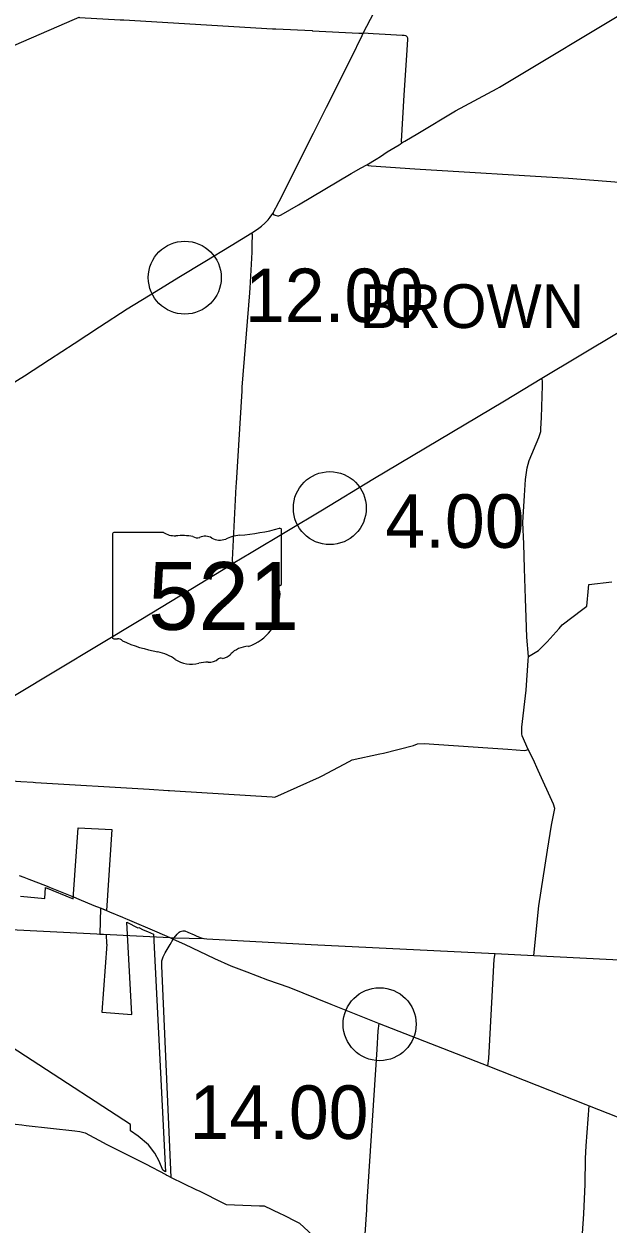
# Model space of a CAD drawing. Extents: x 1597222 to 1925846, y 496284 to 911751.
# Drawn here: x 1821840 to 1833850, y 827893 to 852560 of the extents above; entities that cross this region are included whole.
import ezdxf

# ---------------------------------------------------------------- set-up
doc = ezdxf.new("R2010")
doc.units = 0
for name, color, linetype in [('Default', 7, 'Continuous'), ('GM_X_Corporation', 7, 'Continuous'), ('GM_X_County_Road', 7, 'Continuous'), ('GM_X_State_Route', 7, 'Continuous'), ('GM_X_State_Shield', 7, 'Continuous'), ('GM_X_Township', 7, 'Continuous'), ('GM_X_Township_Road', 7, 'Continuous'), ('GM_X_Township_Text', 7, 'Continuous'), ('GM_X_US_Route', 7, 'Continuous')]:
    doc.layers.add(name, color=color, linetype=linetype)

msp = doc.modelspace()

# ---------------------------------------------------------------- linework, layer by layer
at = {"layer": 'Default'}
for centre in [(1825146, 847346), (1828129, 842608), (1829153, 832000)]:
    msp.add_circle(centre, 750, dxfattribs=at)
at = {"layer": 'GM_X_Corporation'}
msp.add_lwpolyline([(1821769, 834633), (1822268, 834587), (1822281, 834808), (1822854, 834577), (1822956, 836039), (1823645, 836005), (1823540, 834336), (1823415, 834383), (1823397, 833851), (1823528, 833845), (1823535, 833649), (1823542, 833643), (1823444, 832245), (1824058, 832202), (1823955, 834094), (1824182, 833983), (1824200, 833986), (1824290, 833942), (1824382, 833903), (1824500, 833849), (1824747, 828967), (1824696, 828999), (1824623, 829186), (1824531, 829351), (1824401, 829520), (1824191, 829701), (1824029, 829809), (1824031, 829939), (1819982, 832569)], dxfattribs=at)
at = {"layer": 'GM_X_County_Road'}
for points in [[(1827483, 848845), (1828569, 849486), (1828773, 849606), (1828890, 849668)], [(1828890, 849668), (1828890, 849668), (1828924, 849648), (1828977, 849643), (1829879, 849585), (1833037, 849389), (1834076, 849311), (1834469, 849288), (1834642, 849380), (1834781, 849392), (1836063, 849299), (1838431, 849174), (1838783, 849153), (1838998, 849141)], [(1826954, 848664), (1826976, 848639), (1827002, 848628), (1827054, 848615), (1827084, 848617), (1827126, 848635), (1827483, 848845)], [(1824834, 836804), (1824939, 836797), (1826941, 836673), (1827000, 836670), (1827915, 837079), (1827969, 837103), (1828528, 837401), (1828591, 837434), (1829159, 837555), (1829234, 837570), (1829847, 837731), (1829932, 837765), (1830068, 837770), (1831380, 837679), (1831789, 837651), (1832132, 837627), (1832164, 837633), (1832207, 837647), (1832086, 837925), (1832077, 837968), (1832081, 838107), (1832167, 838864), (1832211, 839479), (1832217, 839559), (1832354, 839640), (1832420, 839679), (1832530, 839793), (1832596, 839862), (1832843, 840137), (1832910, 840211), (1833329, 840531), (1833411, 840594), (1833446, 840962), (1833453, 841041), (1833926, 841092)], [(1820825, 837049), (1820913, 837042), (1821680, 836994), (1821777, 836987), (1822028, 836972), (1822074, 836969)], [(1822074, 836969), (1824417, 836829)], [(1824417, 836829), (1824803, 836806), (1824834, 836804), (1824834, 836804)], [(1833284, 827097), (1833354, 828099), (1833377, 828710), (1833389, 829242), (1833401, 829499), (1833463, 830322)]]:
    msp.add_lwpolyline(points, dxfattribs=at)
at = {"layer": 'GM_X_State_Route'}
for points in [[(1824240, 840319), (1825270, 840939), (1826096, 841440), (1826142, 841474), (1826514, 841694), (1827976, 842576), (1829017, 843200), (1831719, 844816), (1832490, 845282), (1838868, 849097), (1838914, 849121), (1838998, 849141), (1839418, 849116)], [(1820468, 838053), (1820655, 838166), (1821648, 838759), (1824240, 840319)]]:
    msp.add_lwpolyline(points, dxfattribs=at)
at = {"layer": 'GM_X_State_Shield'}
for p, q in [((1827137, 841053), (1827137, 842159)), ((1827137, 841053), (1827137, 842159)), ((1823657, 842070), (1823657, 839957)), ((1823657, 842070), (1823657, 839957)), ((1824710, 842107), (1823691, 842107)), ((1824710, 842107), (1823691, 842107)), ((1827137, 841054), (1827137, 841053)), ((1827137, 841054), (1827137, 841053))]:
    msp.add_line(p, q, dxfattribs=at)
for centre, major_axis, start_param, end_param in [((1825898, 844988), (3691, 0), 4.814394, 5.042369), ((1825898, 844988), (3691, 0), 4.814394, 5.042369), ((1827099, 842163), (38.7, 0), 6.141152, 7.989035), ((1827099, 842163), (38.7, 0), 6.141152, 7.989035), ((1823697, 842075), (40.3, 0), 1.712693, 3.28349), ((1823697, 842075), (40.3, 0), 1.712693, 3.28349), ((1824953, 842352), (391, 0), 4.042523, 4.731795), ((1824953, 842352), (391, 0), 4.042523, 4.731795), ((1825083, 840920), (1404, 0), 1.404758, 1.657858), ((1825083, 840920), (1404, 0), 1.404758, 1.657858), ((1825402, 842086), (113, 0), 3.836095, 5.185415), ((1825402, 842086), (113, 0), 3.836095, 5.185415), ((1825567, 841841), (235, 0), 0.950623, 2.079405), ((1825567, 841841), (235, 0), 0.950623, 2.079405), ((1825870, 842176), (282, 0), 4.081561, 5.145723), ((1825870, 842176), (282, 0), 4.081561, 5.145723), ((1826368, 841461), (743, 0), 1.699011, 2.107814), ((1826368, 841461), (743, 0), 1.699011, 2.107814), ((1827128, 840972), (60, 0), 1.883978, 3.671073), ((1827128, 840972), (60, 0), 1.883978, 3.671073), ((1826747, 840833), (360, 0), 5.934695, 6.695948), ((1826747, 840833), (360, 0), 5.934695, 6.695948), ((1827096, 841049), (41.5, 0), 5.05454, 6.418171), ((1827096, 841049), (41.5, 0), 5.05454, 6.418171), ((1827276, 840591), (262, 0), 2.387724, 3.262537), ((1827276, 840591), (262, 0), 2.387724, 3.262537), ((1826104, 840450), (923, 0), 5.101752, 6.440018), ((1826104, 840450), (923, 0), 5.101752, 6.440018), ((1823697, 839952), (40.7, 0), 3.00124, 4.508301), ((1823697, 839952), (40.7, 0), 3.00124, 4.508301), ((1823703, 840168), (310, 0), 4.665946, 4.897461), ((1823703, 840168), (310, 0), 4.665946, 4.897461), ((1823767, 839835), (112, 0), 0.519207, 1.627899), ((1823767, 839835), (112, 0), 0.519207, 1.627899), ((1825180, 841734), (2665, 0), 4.195997, 4.488961), ((1825180, 841734), (2665, 0), 4.195997, 4.488961), ((1826494, 839364), (506, 0), 1.647645, 2.488434), ((1826494, 839364), (506, 0), 1.647645, 2.488434), ((1824385, 839008), (834, 0), 0.823519, 1.323587), ((1824385, 839008), (834, 0), 0.823519, 1.323587), ((1825287, 839824), (529, 0), 4.026481, 4.996735), ((1825287, 839824), (529, 0), 4.026481, 4.996735), ((1825593, 839094), (435, 0), 1.495662, 1.94098), ((1825593, 839094), (435, 0), 1.495662, 1.94098), ((1825632, 839666), (282, 0), 4.691044, 5.507374), ((1825632, 839666), (282, 0), 4.691044, 5.507374), ((1825887, 839462), (79.4, 0), 1.147584, 2.315152), ((1825887, 839462), (79.4, 0), 1.147584, 2.315152), ((1825853, 839752), (298, 0), 4.937069, 5.64225), ((1825853, 839752), (298, 0), 4.937069, 5.64225)]:
    msp.add_ellipse(centre, major_axis=major_axis, ratio=0.8, start_param=start_param, end_param=end_param, dxfattribs=at)
at = {"layer": 'GM_X_Township'}
msp.add_lwpolyline([(1818966, 812859), (1819169, 816826), (1819403, 820562), (1819571, 823253), (1819973, 830336), (1820000, 830812), (1820182, 834021), (1820873, 833984), (1824840, 833781), (1824931, 833776), (1825545, 833759), (1825602, 833752), (1827748, 833636), (1831529, 833453), (1832327, 833414), (1835297, 833263)], dxfattribs=at)
at = {"layer": 'GM_X_Township_Road'}
for points in [[(1829632, 850131), (1829670, 850148), (1829937, 850308), (1830715, 850775), (1831571, 851235), (1831618, 851263), (1834382, 852917), (1834467, 852967), (1834850, 853196), (1834871, 853208)], [(1821238, 851978), (1821378, 852020), (1821474, 852048), (1822880, 852657), (1822973, 852697), (1822981, 852696), (1823816, 852647), (1823896, 852643), (1826953, 852461), (1827020, 852457), (1827766, 852423)], [(1827766, 852423), (1827772, 852422), (1828724, 852374), (1828817, 852370)], [(1829609, 850120), (1829604, 850137), (1829602, 850154), (1829661, 851097), (1829717, 852021), (1829733, 852247), (1829733, 852268), (1829728, 852285), (1829722, 852293), (1829709, 852307), (1829695, 852315), (1829689, 852317), (1829659, 852321), (1829617, 852324), (1829269, 852344), (1829020, 852358), (1828817, 852370)], [(1828890, 849668), (1829079, 849784), (1829169, 849839), (1829310, 849931), (1829553, 850077), (1829575, 850092), (1829609, 850120), (1829632, 850131)], [(1826484, 847033), (1826485, 847041), (1826492, 847131), (1826529, 847868), (1826535, 848025), (1826539, 848226), (1826523, 848267)], [(1826142, 841474), (1826131, 841521), (1826129, 841545), (1826206, 843055), (1826209, 843120), (1826326, 845018), (1826330, 845093), (1826484, 847033)], [(1832217, 839559), (1832181, 839958), (1832166, 840360), (1832150, 840747), (1832131, 841365), (1832119, 841876), (1832100, 842311), (1832130, 842865), (1832154, 843199), (1832190, 843436), (1832231, 843590), (1832429, 844063), (1832467, 844186), (1832471, 844240), (1832481, 844468), (1832506, 845131), (1832505, 845224), (1832490, 845282)], [(1832327, 833414), (1832426, 834435), (1832607, 835575), (1832687, 836093), (1832759, 836431), (1832731, 836526), (1832414, 837215), (1832308, 837446), (1832207, 837647)], [(1824865, 828850), (1824672, 833200), (1824677, 833301), (1824702, 833383), (1824742, 833469), (1824845, 833635), (1824911, 833750)], [(1824911, 833750), (1824931, 833776), (1824988, 833851), (1825028, 833889), (1825051, 833904), (1825079, 833915), (1825108, 833920), (1825149, 833917), (1825208, 833895), (1825339, 833834), (1825392, 833810), (1825482, 833777), (1825540, 833760)], [(1825540, 833760), (1825545, 833759), (1825602, 833752), (1827748, 833636), (1831529, 833453), (1832327, 833414)], [(1831379, 831146), (1831397, 831297), (1831511, 833337), (1831529, 833453)], [(1832327, 833414), (1835297, 833263), (1838313, 833094), (1838887, 833066), (1838934, 833082)], [(1828797, 826781), (1828889, 828182), (1828892, 828243), (1829101, 831483), (1829126, 831863), (1829142, 832016)], [(1820010, 830806), (1820042, 830778), (1820145, 830662), (1820205, 830609), (1820524, 830257), (1820580, 830196), (1820656, 830123), (1820728, 830055), (1820936, 830023), (1821010, 830011), (1821798, 829929), (1821888, 829919), (1822885, 829807), (1822989, 829796), (1823040, 829782), (1823095, 829767), (1823466, 829565), (1823529, 829531), (1824286, 829155), (1824340, 829128), (1824755, 828908)], [(1824755, 828908), (1824759, 828906), (1824806, 828881), (1824854, 828855), (1824865, 828850), (1825377, 828604), (1825454, 828567), (1825926, 828329), (1825999, 828292), (1826685, 828268), (1826777, 828264), (1827111, 828106), (1827169, 828078), (1827454, 827939), (1827508, 827913), (1828046, 827407), (1828188, 827254), (1828471, 826984), (1828536, 826919), (1828620, 826843), (1828679, 826807), (1828738, 826785), (1828797, 826781)]]:
    msp.add_lwpolyline(points, dxfattribs=at)
at = {"layer": 'GM_X_US_Route'}
for points in [[(1828794, 852323), (1828817, 852370), (1829042, 852803), (1829388, 853493), (1829567, 853847)], [(1826523, 848267), (1826643, 848340), (1826727, 848406), (1826792, 848465), (1826862, 848537), (1826902, 848592), (1826954, 848664), (1827089, 848914), (1827795, 850319), (1828063, 850849), (1828568, 851857), (1828794, 852323)], [(1815985, 842997), (1816140, 843045), (1816516, 843159), (1818004, 843604), (1819466, 844036), (1819970, 844186), (1820078, 844226), (1820154, 844261), (1820230, 844302), (1820378, 844395), (1820678, 844582), (1820789, 844650), (1821371, 845021), (1821564, 845146), (1821850, 845326), (1822366, 845660), (1822875, 845990), (1823392, 846332), (1823964, 846703), (1824557, 847070), (1825025, 847354), (1825562, 847681), (1826103, 848010), (1826523, 848267)], [(1821742, 835058), (1821837, 835019), (1821938, 834981)], [(1821938, 834981), (1822282, 834851), (1822381, 834811)], [(1822381, 834811), (1822857, 834621), (1822968, 834573)], [(1822968, 834573), (1823279, 834440), (1823404, 834391), (1823504, 834351)], [(1823504, 834351), (1823539, 834337), (1823602, 834310)], [(1823602, 834310), (1823863, 834198), (1823927, 834172), (1823961, 834158), (1824572, 833896)], [(1824572, 833896), (1824840, 833781), (1824911, 833750), (1825142, 833644), (1825759, 833347), (1826092, 833198), (1826420, 833073), (1826849, 832915), (1827284, 832761), (1828153, 832411), (1829142, 832016), (1831379, 831146), (1833393, 830350), (1833463, 830322), (1836024, 829315)]]:
    msp.add_lwpolyline(points, dxfattribs=at)

# ---------------------------------------------------------------- texts
at = {"layer": 'Default'}
for s, p in [('12.00', (1826385, 846432)), ('4.00', (1829270, 841792)), ('14.00', (1825243, 829642))]:
    msp.add_text(s, height=1100, dxfattribs=at).set_placement(p)
at = {"layer": 'GM_X_State_Shield'}
msp.add_text('521', height=1392.2, dxfattribs=at).set_placement((1824394, 840106))
msp.add_text('521', height=1392.2, dxfattribs=at).set_placement((1824394, 840106))
at = {"layer": 'GM_X_Township_Text'}
msp.add_text('BROWN', height=900, rotation=0, dxfattribs=at).set_placement((1828743, 846310))

doc.saveas('drawing.dxf')
